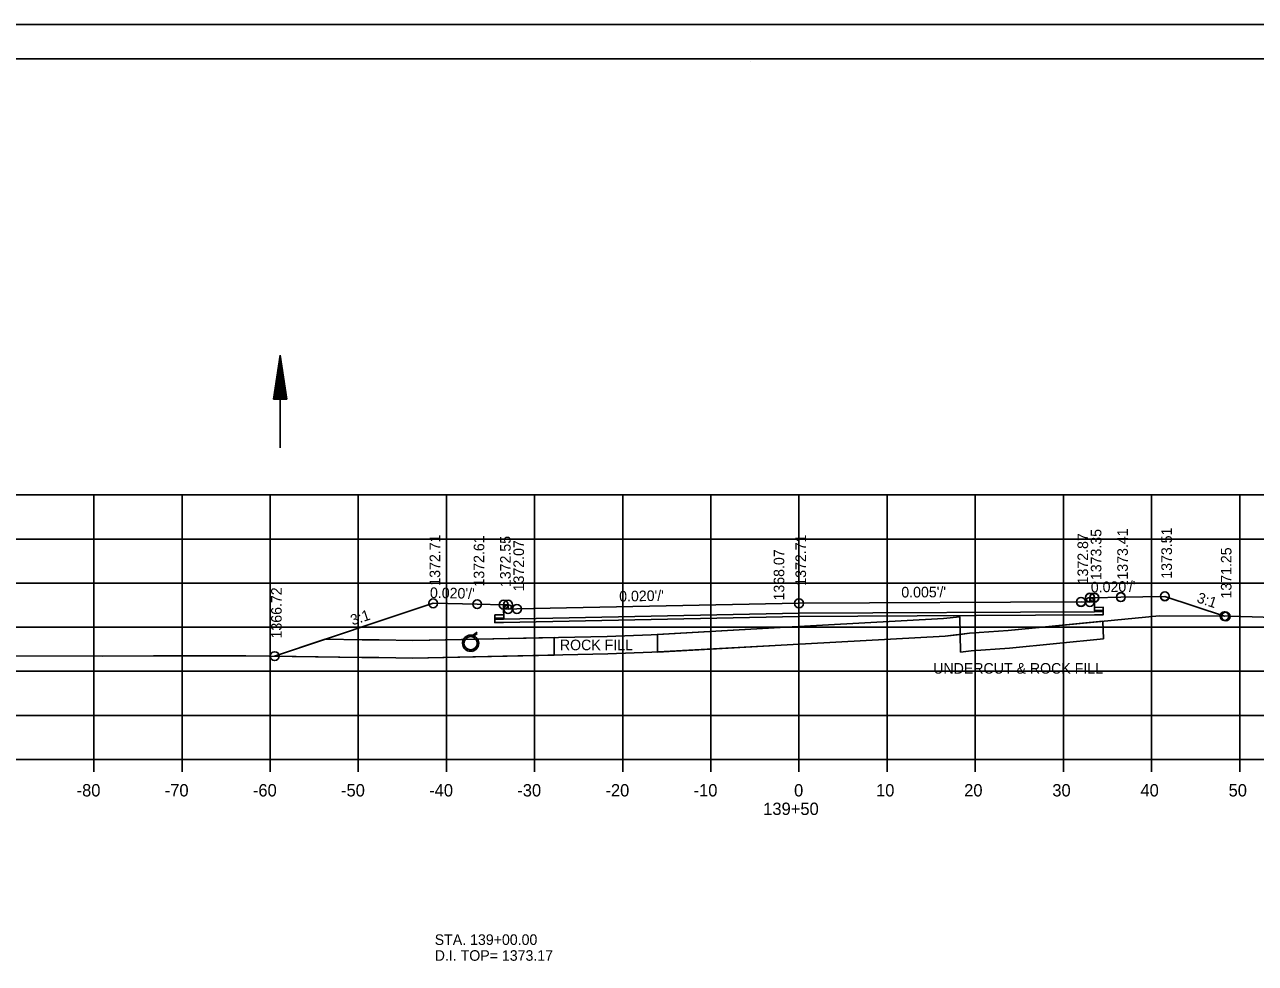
# Model space of a CAD drawing. Extents: x 1374311 to 1383814, y 384102 to 406278.
# Drawn here: x 1381540.8 to 1381680.4, y 389124.9 to 389231.4 of the extents above; entities that cross this region are included whole.
import ezdxf

# ---------------------------------------------------------------- set-up
doc = ezdxf.new("R2010")
doc.units = 0
for name, color, linetype in [('R_Axis', 7, 'Continuous'), ('R_Axis Annot', 7, 'Continuous'), ('R_Border', 7, 'Continuous'), ('R_Draft', 7, 'Continuous'), ('R_Exist Surface', 7, 'Continuous'), ('R_Fin Surface', 7, 'Continuous'), ('R_Grid', 7, 'Continuous'), ('R_No Plot', 7, 'Continuous'), ('R_Water', 7, 'Continuous'), ('R_Water Annot', 7, 'Continuous'), ('R_Xsect Elev', 7, 'Continuous'), ('R_Xsect Slope', 7, 'Continuous')]:
    doc.layers.add(name, color=color, linetype=linetype)

msp = doc.modelspace()

# ---------------------------------------------------------------- linework, layer by layer
at = {"layer": 'R_Axis'}
for p, q in [((1381488.66, 389148.02), (1381768.66, 389148.02)), ((1381548.66, 389146.62), (1381548.66, 389148.02)), ((1381558.66, 389146.62), (1381558.66, 389148.02)), ((1381568.66, 389146.62), (1381568.66, 389148.02)), ((1381578.66, 389146.62), (1381578.66, 389148.02)), ((1381588.66, 389146.62), (1381588.66, 389148.02)), ((1381598.66, 389146.62), (1381598.66, 389148.02)), ((1381608.66, 389146.62), (1381608.66, 389148.02)), ((1381618.66, 389146.62), (1381618.66, 389148.02)), ((1381628.66, 389146.62), (1381628.66, 389148.02)), ((1381638.66, 389146.62), (1381638.66, 389148.02)), ((1381648.66, 389146.62), (1381648.66, 389148.02)), ((1381658.66, 389146.62), (1381658.66, 389148.02)), ((1381668.66, 389146.62), (1381668.66, 389148.02)), ((1381678.66, 389146.62), (1381678.66, 389148.02))]:
    msp.add_line(p, q, dxfattribs=at)
at = {"layer": 'R_Border'}
for p, q in [((1381470.66, 389227.48), (1381786.84, 389227.48)), ((1381623.18, 389227.22), (1381623.18, 389227.22)), ((1381623.18, 389227.22), (1381623.18, 389227.22))]:
    msp.add_line(p, q, dxfattribs=at)
at = {"layer": 'R_Draft'}
for p, q in [((1381569.04, 389188.89), (1381569.79, 389193.89)), ((1381570.54, 389188.89), (1381569.79, 389193.89)), ((1381569.17, 389188.89), (1381569.79, 389193.05)), ((1381570.42, 389188.89), (1381569.79, 389193.05)), ((1381569.3, 389188.89), (1381569.79, 389192.19)), ((1381569.42, 389188.89), (1381569.79, 389191.36)), ((1381570.29, 389188.89), (1381569.79, 389192.19)), ((1381570.17, 389188.89), (1381569.79, 389191.36)), ((1381569.55, 389188.89), (1381569.79, 389190.51)), ((1381569.68, 389188.89), (1381569.79, 389189.68)), ((1381570.04, 389188.89), (1381569.79, 389190.51)), ((1381569.91, 389188.89), (1381569.79, 389189.68)), ((1381570.54, 389188.89), (1381569.04, 389188.89))]:
    msp.add_line(p, q, dxfattribs=at)
at = {"layer": 'R_Exist Surface'}
for p, q in [((1381592.15, 389162.47), (1381591.63, 389162.08)), ((1381592.15, 389160.64), (1381591.63, 389160.25))]:
    msp.add_line(p, q, dxfattribs=at)
msp.add_lwpolyline([(1381488.66, 389158.62), (1381493.26, 389158.75), (1381500.95, 389158.96), (1381512.79, 389159.25), (1381518.42, 389159.42), (1381534.02, 389159.76), (1381534.34, 389159.77), (1381535.35, 389159.78), (1381549.59, 389159.75), (1381555.41, 389159.78), (1381565.91, 389159.78), (1381579.06, 389159.59), (1381581, 389159.57), (1381584.85, 389159.51), (1381606.96, 389159.99), (1381611.98, 389160.17), (1381626.63, 389160.98), (1381645.23, 389162), (1381648.01, 389162.33), (1381652.39, 389162.64), (1381669.54, 389164.31), (1381677.54, 389164.27), (1381683.84, 389164.07)], dxfattribs=at)
msp.add_circle((1381591.4, 389161.2), 0.917, dxfattribs=at)
at = {"layer": 'R_Fin Surface'}
for p, q in [((1381646.93, 389162.2), (1381646.89, 389164.21)), ((1381600.87, 389161.85), (1381592.19, 389161.67)), ((1381600.87, 389161.85), (1381600.87, 389159.85)), ((1381600.87, 389159.85), (1381600.87, 389161.85)), ((1381612.61, 389162.21), (1381612.61, 389160.2)), ((1381612.61, 389162.21), (1381612.61, 389160.2)), ((1381646.93, 389162.2), (1381646.97, 389160.19)), ((1381574.92, 389161.65), (1381569.17, 389159.74)), ((1381569.17, 389159.74), (1381579.06, 389159.59)), ((1381579.06, 389159.59), (1381581, 389159.57))]:
    msp.add_line(p, q, dxfattribs=at)
for points in [[(1381569.17, 389159.74), (1381587.15, 389165.73), (1381592.15, 389165.63), (1381595.15, 389165.57), (1381595.65, 389165.57), (1381595.66, 389165.07), (1381596.66, 389165.09), (1381628.66, 389165.73), (1381660.66, 389165.88), (1381661.66, 389165.86), (1381661.67, 389166.36), (1381662.17, 389166.36), (1381665.17, 389166.42), (1381670.17, 389166.52), (1381676.93, 389164.27)], [(1381662.17, 389166.02), (1381662.18, 389164.91), (1381663.18, 389164.93), (1381663.17, 389164.43), (1381662.17, 389164.42), (1381628.66, 389164.24), (1381595.15, 389163.57), (1381594.15, 389163.55), (1381594.16, 389164.05), (1381595.16, 389164.06), (1381595.15, 389165.21)], [(1381574.92, 389161.65), (1381579.09, 389161.59), (1381581.03, 389161.57), (1381584.84, 389161.51), (1381606.9, 389161.98), (1381611.89, 389162.17), (1381626.52, 389162.98), (1381645.06, 389163.99), (1381646.89, 389164.21), (1381646.97, 389160.19)], [(1381646.89, 389164.21), (1381645.06, 389163.99), (1381626.52, 389162.98), (1381612.61, 389162.21)], [(1381663.15, 389163.69), (1381652.39, 389162.64), (1381648.01, 389162.33), (1381646.93, 389162.2)], [(1381646.97, 389160.19), (1381648.2, 389160.34), (1381652.56, 389160.65), (1381663.19, 389161.7), (1381663.15, 389163.69)], [(1381646.97, 389160.19), (1381648.2, 389160.34), (1381652.56, 389160.65), (1381663.19, 389161.7), (1381663.15, 389163.69)], [(1381612.61, 389160.2), (1381626.63, 389160.98), (1381645.23, 389162), (1381646.93, 389162.2)], [(1381590.59, 389161.63), (1381584.84, 389161.51), (1381581.03, 389161.57), (1381579.09, 389161.59), (1381574.92, 389161.65)], [(1381574.92, 389161.65), (1381574.92, 389161.65)], [(1381581, 389159.57), (1381584.85, 389159.51), (1381600.87, 389159.85)]]:
    msp.add_lwpolyline(points, dxfattribs=at)
msp.add_arc((1381591.4, 389161.2), 0.917, 151.8568, 30.6128, dxfattribs=at)
at = {"layer": 'R_Grid'}
for p, q in [((1381488.66, 389178.02), (1381768.66, 389178.02)), ((1381548.66, 389148.02), (1381548.66, 389178.02)), ((1381558.66, 389148.02), (1381558.66, 389178.02)), ((1381568.66, 389148.02), (1381568.66, 389178.02)), ((1381578.66, 389148.02), (1381578.66, 389178.02)), ((1381588.66, 389148.02), (1381588.66, 389178.02)), ((1381598.66, 389148.02), (1381598.66, 389178.02)), ((1381608.66, 389148.02), (1381608.66, 389178.02)), ((1381618.66, 389148.02), (1381618.66, 389178.02)), ((1381628.66, 389148.02), (1381628.66, 389178.02)), ((1381638.66, 389148.02), (1381638.66, 389178.02)), ((1381648.66, 389148.02), (1381648.66, 389178.02)), ((1381658.66, 389148.02), (1381658.66, 389178.02)), ((1381668.66, 389148.02), (1381668.66, 389178.02)), ((1381678.66, 389148.02), (1381678.66, 389178.02)), ((1381488.66, 389173.02), (1381768.66, 389173.02)), ((1381488.66, 389168.02), (1381768.66, 389168.02)), ((1381488.66, 389163.02), (1381768.66, 389163.02)), ((1381488.66, 389158.02), (1381768.66, 389158.02)), ((1381488.66, 389153.02), (1381768.66, 389153.02)), ((1381488.66, 389148.02), (1381768.66, 389148.02))]:
    msp.add_line(p, q, dxfattribs=at)
at = {"layer": 'R_No Plot'}
msp.add_line((1381458.26, 389231.37), (1381791.59, 389231.37), dxfattribs=at)
for points in [[(1381458.25, 389231.37), (1381791.59, 389231.37), (1381791.59, 389018.04), (1381458.25, 389018.04)], [(1381704.58, 389227.48), (1381704.58, 389217.6), (1381740.31, 389217.6), (1381740.31, 389214.68), (1381763.51, 389214.68), (1381763.51, 389191.46), (1381786.84, 389191.46), (1381786.84, 389022.02), (1381470.66, 389022.02), (1381470.66, 389227.48)], [(1381569.17, 389159.74), (1381579.06, 389159.59), (1381581, 389159.57), (1381584.85, 389159.51), (1381606.96, 389159.99), (1381611.98, 389160.17), (1381626.63, 389160.98), (1381645.23, 389162), (1381648.01, 389162.33), (1381652.39, 389162.64), (1381669.54, 389164.31), (1381676.93, 389164.27), (1381670.17, 389166.52), (1381665.17, 389166.42), (1381662.17, 389166.36), (1381662.18, 389165.27), (1381663.18, 389165.29), (1381663.17, 389164.79), (1381662.17, 389164.78), (1381628.66, 389164.6), (1381595.15, 389163.93), (1381594.15, 389163.91), (1381594.16, 389164.41), (1381595.16, 389164.42), (1381595.15, 389165.57), (1381592.15, 389165.63), (1381587.15, 389165.73)]]:
    msp.add_lwpolyline(points, close=True, dxfattribs=at)
for centre in [(1381587.15, 389165.73), (1381587.15, 389165.73), (1381587.15, 389165.73), (1381592.15, 389165.63), (1381592.15, 389165.63), (1381592.15, 389165.63), (1381595.15, 389165.57), (1381595.15, 389165.57), (1381595.15, 389165.57), (1381595.65, 389165.57), (1381595.65, 389165.57), (1381595.65, 389165.57), (1381628.66, 389165.73), (1381628.66, 389165.73), (1381628.66, 389165.73), (1381660.66, 389165.9), (1381660.66, 389165.9), (1381660.66, 389165.88), (1381661.66, 389165.88), (1381661.67, 389166.38), (1381661.67, 389166.38), (1381661.67, 389166.36), (1381662.17, 389166.38), (1381662.17, 389166.38), (1381662.17, 389166.36), (1381665.17, 389166.44), (1381665.17, 389166.44), (1381665.17, 389166.42), (1381670.17, 389166.54), (1381670.17, 389166.54), (1381670.17, 389166.52), (1381595.66, 389165.07), (1381596.66, 389165.09), (1381596.66, 389165.09), (1381596.66, 389165.09), (1381676.93, 389164.27), (1381676.99, 389164.27), (1381677.09, 389164.23), (1381569.17, 389159.74), (1381569.17, 389159.74), (1381569.17, 389159.74), (1381569.17, 389159.74), (1381569.17, 389159.74), (1381569.17, 389159.74)]:
    msp.add_circle(centre, 0.5, dxfattribs=at)
at = {"layer": 'R_Water'}
for p, q in [((1381569.79, 389183.38), (1381569.79, 389193.89)), ((1381592.15, 389162.3), (1381591.63, 389161.91)), ((1381592.15, 389160.8), (1381591.63, 389160.41))]:
    msp.add_line(p, q, dxfattribs=at)
msp.add_circle((1381591.4, 389161.2), 0.75, dxfattribs=at)

# ---------------------------------------------------------------- texts
at = {"layer": 'R_Axis Annot'}
for s, p in [('-80', (1381546.7, 389143.82)), ('-70', (1381556.7, 389143.82)), ('-60', (1381566.7, 389143.82)), ('-50', (1381576.7, 389143.82)), ('-40', (1381586.7, 389143.82)), ('-30', (1381596.7, 389143.82)), ('-20', (1381606.7, 389143.82)), ('-10', (1381616.7, 389143.82)), ('0', (1381628.1, 389143.82)), ('10', (1381637.4, 389143.82)), ('20', (1381647.4, 389143.82)), ('30', (1381657.4, 389143.82)), ('40', (1381667.4, 389143.82)), ('50', (1381677.4, 389143.82)), ('139+50', (1381624.6, 389141.72))]:
    msp.add_text(s, height=1.4, dxfattribs=at).set_placement(p)
at = {"layer": 'R_Fin Surface'}
for s, p in [('ROCK FILL', (1381601.53, 389160.41)), ('UNDERCUT & ROCK FILL', (1381643.89, 389157.75))]:
    msp.add_text(s, height=1.2, dxfattribs=at).set_placement(p)
at = {"layer": 'R_Water Annot'}
for s, p in [('STA. 139+00.00', (1381587.33, 389126.98)), ('D.I. TOP= 1373.17', (1381587.33, 389125.18))]:
    msp.add_text(s, height=1.2, dxfattribs=at).set_placement(p)
at = {"layer": 'R_Xsect Elev'}
for s, p in [('1372.71', (1381587.95, 389167.73)), ('1372.61', (1381592.95, 389167.63)), ('1372.55', (1381595.95, 389167.57)), ('1372.71', (1381629.46, 389167.73)), ('1372.87', (1381661.46, 389167.88)), ('1373.35', (1381662.97, 389168.36)), ('1373.41', (1381665.97, 389168.42)), ('1373.51', (1381670.97, 389168.52)), ('1372.07', (1381597.46, 389167.09)), ('1368.07', (1381626.99, 389166.05)), ('1371.25', (1381677.73, 389166.27)), ('1366.72', (1381569.97, 389161.74))]:
    msp.add_text(s, height=1.2, rotation=90, dxfattribs=at).set_placement(p)
at = {"layer": 'R_Xsect Slope'}
for s, rotation, p in [("0.020'/'", 358.8542, (1381586.78, 389166.34)), ("0.020'/'", 1.1458, (1381608.27, 389165.92)), ("0.005'/'", 0.2753, (1381640.27, 389166.39)), ("0.020'/'", 1.1458, (1381661.78, 389166.96)), ('3:1', 341.5651, (1381673.71, 389165.87)), ('3:1', 18.4349, (1381578, 389163.21))]:
    msp.add_text(s, height=1.2, rotation=rotation, dxfattribs=at).set_placement(p)

doc.saveas('drawing.dxf')
